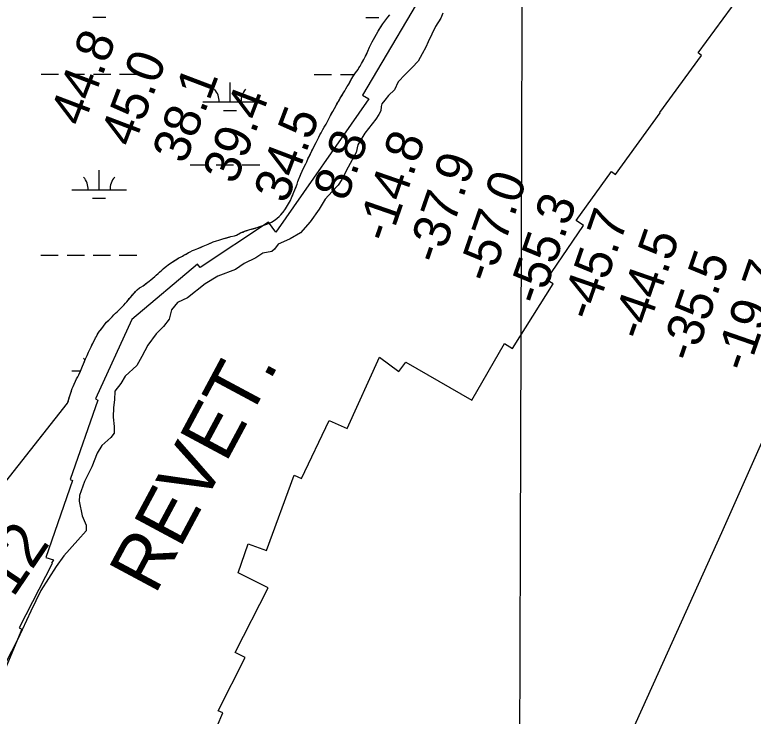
# Model space of a CAD drawing. Extents: x 3148686 to 3186545, y 916144 to 941516.
# Drawn here: x 3159855 to 3161212, y 930448 to 931737 of the extents above; entities that cross this region are included whole.
import ezdxf

# ---------------------------------------------------------------- set-up
doc = ezdxf.new("R2010")
doc.units = 0
for name, color, linetype in [('V-GRID-MAJR', 7, 'Continuous'), ('V-RIVR-EDGE', 7, 'Continuous'), ('V-RIVR-IDEN', 7, 'Continuous'), ('V-RIVR-RANG', 7, 'Continuous'), ('V-RRAP-RVMT', 7, 'Continuous'), ('V-RRAP-RVMT-IDEN', 7, 'Continuous'), ('V-SITE-VEGE', 7, 'Continuous'), ('V-TOPO-BNDY', 7, 'Continuous'), ('V-WETL-SWMP', 7, 'Continuous')]:
    doc.layers.add(name, color=color, linetype=linetype)

msp = doc.modelspace()

# ---------------------------------------------------------------- linework, layer by layer
at = {"layer": 'V-GRID-MAJR'}
msp.add_spline([(3160753.613, 921529.2320000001), (3160773.887, 927589.627), (3160794.169, 933652.633), (3160814.452, 939715.688), (3160814.461, 939718.2490000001)], degree=3, dxfattribs=at)
at = {"layer": 'V-RIVR-EDGE'}
for points in [[(3160641.8411565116, 931740.028499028), (3160637.9178512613, 931730.8187604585), (3160628.306173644, 931715.5949923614), (3160614.76154594, 931687.260977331), (3160610.837363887, 931677.6966470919), (3160604.070310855, 931665.6571895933), (3160596.5896904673, 931651.846527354), (3160585.2138225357, 931640.173059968), (3160572.4160807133, 931627.0847331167), (3160559.6174620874, 931613.6418145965), (3160553.199739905, 931599.4739302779), (3160542.180217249, 931588.5087694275), (3160535.4219322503, 931580.0152286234), (3160529.7326830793, 931573.6466074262), (3160528.6566328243, 931568.6849544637), (3160527.9272830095, 931560.5310996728), (3160524.3647070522, 931553.8026259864), (3160518.6701970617, 931545.3064547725), (3160498.749933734, 931519.8249555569), (3160485.931148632, 931498.2264286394), (3160482.7047514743, 931484.0506530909), (3160468.0998559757, 931457.1376351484), (3160456.3422154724, 931434.4727028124), (3160449.578669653, 931423.8516119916), (3160438.5582701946, 931412.5318594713), (3160425.7578979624, 931398.3797576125), (3160414.3653707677, 931379.9690485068), (3160398.3508766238, 931356.6054544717), (3160380.570438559, 931336.0829778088), (3160361.3961843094, 931325.4925751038)], [(3160361.3961843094, 931325.4925751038), (3160349.3251618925, 931319.4943280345), (3160339.0323586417, 931315.6192469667), (3160332.626034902, 931306.0610543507), (3160327.65122989, 931301.8182295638), (3160311.332121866, 931298.6672374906), (3160298.19206362, 931290.5440708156), (3160276.8902593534, 931279.9589289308), (3160260.905576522, 931268.6514516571), (3160228.2533316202, 931256.6760007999), (3160205.169800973, 931242.5493262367), (3160172.484237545, 931217.0993919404), (3160154.023550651, 931208.2801939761), (3160142.9978903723, 931194.8328914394), (3160138.70070378, 931177.8230129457), (3160128.737941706, 931164.0184883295), (3160115.2301397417, 931150.577323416), (3160099.5763748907, 931129.6949942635), (3160088.887770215, 931109.1549815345), (3160079.271708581, 931092.1582550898), (3160057.947984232, 931072.7083214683), (3160050.1136489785, 931059.2531277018), (3160039.0871118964, 931045.4512334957), (3160038.3384724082, 931029.4963619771), (3160036.884156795, 931014.9616107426), (3160036.1320100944, 930997.5883725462), (3160037.8628818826, 930980.5635883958), (3160037.831316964, 930967.7982882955), (3160031.7848457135, 930960.366768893), (3160015.43680318, 930945.5142517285), (3160006.5369393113, 930931.352505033), (3159996.8998343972, 930905.8455785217), (3159983.35959071, 930879.2845218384), (3159974.4307923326, 930853.421250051), (3159973.6953048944, 930842.7852535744), (3159978.947542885, 930815.8231346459), (3159986.706473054, 930798.7834448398), (3159986.6810457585, 930788.5002864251), (3159971.036925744, 930771.518465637), (3159945.0798360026, 930742.5059553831), (3159931.557128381, 930723.036732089), (3159903.0801944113, 930678.7829176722), (3159884.5467328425, 930640.5326111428), (3159861.0174229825, 930589.5292797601), (3159837.5021419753, 930544.1994150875)]]:
    msp.add_lwpolyline(points, dxfattribs=at)
at = {"layer": 'V-RRAP-RVMT'}
for points in [[(3160778.362000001, 932090.9169999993), (3160623.011000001, 931820.1139999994), (3160628.223000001, 931816.6929999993), (3160494.3570000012, 931589.4709999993), (3160505.799000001, 931582.6299999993), (3160335.192000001, 931337.4799999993), (3160321.716000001, 931355.9769999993), (3160196.112000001, 931272.4869999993), (3160190.900000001, 931278.4419999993), (3160070.636000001, 931176.8989999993), (3160003.384000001, 931030.8869999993), (3160007.834000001, 931028.7969999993), (3159956.918000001, 930882.8799999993), (3159961.494000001, 930881.2329999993), (3159912.106000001, 930739.7519999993), (3159926.120000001, 930735.1229999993), (3159923.006000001, 930729.0119999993), (3159923.647000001, 930728.6839999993), (3159863.236000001, 930610.1979999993), (3159868.342000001, 930607.6079999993), (3159814.852000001, 930481.5139999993)], [(3160265.567000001, 930711.5469999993), (3160284.251000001, 930764.4829999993), (3160318.063000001, 930752.0679999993), (3160368.908000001, 930890.7779999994), (3160382.382000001, 930884.9509999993), (3160432.973000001, 930991.4859999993), (3160466.277000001, 930976.5379999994), (3160525.765000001, 931107.6479999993), (3160560.848000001, 931081.2989999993), (3160573.811000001, 931098.6799999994), (3160695.159000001, 931028.6119999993), (3160755.409000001, 931132.9829999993), (3160770.137000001, 931123.7439999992), (3160844.331000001, 931242.4809999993), (3160832.660000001, 931249.8039999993), (3160900.153000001, 931349.9039999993), (3160886.722000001, 931358.9559999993), (3160952.015000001, 931448.8319999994), (3160958.946000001, 931443.7649999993), (3161041.253000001, 931557.0439999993), (3161040.915000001, 931557.2889999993), (3161117.333000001, 931662.4569999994), (3161111.1780000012, 931666.9029999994), (3161187.612000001, 931772.0799999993)], [(3159946.181000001, 929558.8359999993), (3159956.159000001, 929554.5989999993), (3160010.860000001, 929683.4019999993), (3159995.416000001, 929689.9789999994), (3160047.447000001, 929812.3709999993), (3160034.780000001, 929817.7679999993), (3160086.752000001, 929940.1549999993), (3160053.551000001, 929954.3769999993), (3160105.559000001, 930076.7079999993), (3160092.637000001, 930082.2549999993), (3160144.613000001, 930204.6469999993), (3160142.062000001, 930205.7159999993), (3160194.031000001, 930328.1279999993), (3160185.721000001, 930331.6589999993), (3160237.700000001, 930454.0649999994), (3160228.971000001, 930457.8329999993), (3160278.719000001, 930555.5589999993), (3160260.308000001, 930564.9589999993), (3160320.700000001, 930683.4469999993), (3160265.567000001, 930711.5469999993)]]:
    msp.add_lwpolyline(points, dxfattribs=at)
at = {"layer": 'V-SITE-VEGE'}
for p, q in [((3160540.677, 931732.7579999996), (3160544.257, 931737.1839999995)), ((3160531.543, 931720.2939999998), (3160540.677, 931732.7579999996)), ((3160523.0130000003, 931706.8359999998), (3160531.543, 931720.2939999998)), ((3160512.116, 931687.5559999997), (3160519.843, 931701.4129999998)), ((3160519.843, 931701.4129999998), (3160523.0130000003, 931706.8359999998)), ((3160507.3680000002, 931677.7219999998), (3160512.116, 931687.5559999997)), ((3160499.86, 931660.8609999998), (3160504.21, 931670.0949999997)), ((3160504.21, 931670.0949999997), (3160507.3680000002, 931677.7219999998)), ((3160496.694, 931654.6409999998), (3160499.86, 931660.8609999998)), ((3160487.773, 931639.5759999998), (3160489.958, 931642.5909999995)), ((3160489.958, 931642.5909999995), (3160492.5330000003, 931647.4099999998)), ((3160492.5330000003, 931647.4099999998), (3160496.694, 931654.6409999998)), ((3160478.842, 931626.7139999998), (3160481.4220000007, 931630.1309999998)), ((3160481.4220000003, 931630.1309999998), (3160485.989, 931636.7639999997)), ((3160485.989, 931636.7639999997), (3160487.773, 931639.5759999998)), ((3160468.1410000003, 931608.0369999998), (3160473.488, 931617.8749999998)), ((3160473.488, 931617.8749999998), (3160476.659, 931623.2979999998)), ((3160476.659, 931623.2979999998), (3160478.842, 931626.7139999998)), ((3160463.779, 931600.8049999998), (3160466.355, 931605.2229999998)), ((3160466.355, 931605.2229999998), (3160468.1410000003, 931608.0369999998)), ((3160453.467, 931583.9319999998), (3160459.615, 931593.9729999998)), ((3160459.615, 931593.9729999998), (3160461.596, 931597.5899999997)), ((3160461.596, 931597.5899999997), (3160463.779, 931600.8049999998)), ((3160442.568, 931565.0529999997), (3160453.467, 931583.9319999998)), ((3160439.598, 931559.6299999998), (3160442.568, 931565.0529999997)), ((3160430.29, 931542.3629999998), (3160435.238, 931551.9989999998)), ((3160435.238, 931551.9989999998), (3160439.598, 931559.6299999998)), ((3160423.554, 931530.3129999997), (3160427.324, 931536.3399999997)), ((3160427.324, 931536.3399999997), (3160430.29, 931542.3629999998)), ((3160415.829, 931516.2579999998), (3160418.008, 931520.0729999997)), ((3160418.008, 931520.0729999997), (3160421.174, 931526.2969999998)), ((3160421.174, 931526.2969999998), (3160423.554, 931530.3129999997)), ((3160408.9050000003, 931502.2059999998), (3160413.8510000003, 931512.0429999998)), ((3160413.8510000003, 931512.0429999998), (3160415.829, 931516.2579999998)), ((3160400.987, 931486.7479999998), (3160406.926, 931497.9919999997)), ((3160406.926, 931497.9919999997), (3160408.9050000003, 931502.2059999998)), ((3160394.659, 931473.5019999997), (3160400.987, 931486.7479999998)), ((3160389.916, 931462.8619999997), (3160391.894, 931467.0789999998)), ((3160391.894, 931467.0789999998), (3160394.659, 931473.5019999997)), ((3160383.387, 931449.8139999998), (3160387.736, 931459.0469999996)), ((3160387.736, 931459.0469999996), (3160389.916, 931462.8619999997)), ((3160375.489, 931430.9519999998), (3160381.015, 931444.3929999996)), ((3160381.015, 931444.3929999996), (3160383.387, 931449.8139999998)), ((3160369.9760000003, 931415.1089999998), (3160373.917, 931425.9409999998)), ((3160373.917, 931425.9409999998), (3160375.489, 931430.9519999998)), ((3160363.857, 931400.4619999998), (3160368.197, 931411.2959999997)), ((3160368.197, 931411.2959999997), (3160369.9760000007, 931415.1089999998)), ((3160361.68, 931396.0439999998), (3160363.857, 931400.4619999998)), ((3160354.348, 931383.3919999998), (3160358.313, 931389.8199999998)), ((3160358.313, 931389.8199999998), (3160361.68, 931396.0439999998)), ((3160344.221, 931369.3219999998), (3160348.593, 931374.5499999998)), ((3160348.593, 931374.5499999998), (3160352.7630000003, 931380.5779999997)), ((3160352.7630000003, 931380.5779999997), (3160354.348, 931383.3919999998)), ((3160326.882, 931356.0099999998), (3160333.4620000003, 931360.4519999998)), ((3160333.4620000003, 931360.4519999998), (3160341.036, 931366.0999999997)), ((3160341.036, 931366.0999999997), (3160344.221, 931369.3219999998)), ((3160286.93, 931342.1669999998), (3160300.518, 931345.8499999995)), ((3160300.518, 931345.8499999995), (3160305.5130000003, 931347.6789999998)), ((3160305.5130000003, 931347.6789999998), (3160314.703, 931350.7339999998)), ((3160314.703, 931350.7339999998), (3160318.498, 931352.1579999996)), ((3160318.498, 931352.1579999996), (3160326.882, 931356.0099999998)), ((3160252.1750000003, 931329.3549999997), (3160258.772, 931330.996)), ((3160258.772, 931330.9959999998), (3160262.966, 931332.2199999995)), ((3160262.966, 931332.2199999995), (3160270.151, 931336.0639999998)), ((3160270.151, 931336.0639999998), (3160277.339, 931339.1099999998)), ((3160277.339, 931339.1099999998), (3160286.93, 931342.1669999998)), ((3160210.6210000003, 931315.5019999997), (3160219.805, 931319.56)), ((3160219.805, 931319.5599999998), (3160226, 931321.3969999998)), ((3160226, 931321.3969999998), (3160229.9930000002, 931322.8219999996)), ((3160229.9930000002, 931322.8219999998), (3160233.991, 931324.0469999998)), ((3160233.991, 931324.0469999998), (3160237.784, 931325.4679999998)), ((3160237.784, 931325.4679999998), (3160252.1750000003, 931329.3549999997)), ((3160177.673, 931301.4999999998), (3160182.0640000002, 931303.7279999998)), ((3160182.0640000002, 931303.7279999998), (3160185.46, 931305.1499999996)), ((3160185.46, 931305.1499999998), (3160188.657, 931306.1679999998)), ((3160188.657, 931306.1679999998), (3160191.653, 931307.3859999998)), ((3160191.653, 931307.3859999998), (3160201.434, 931311.6459999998)), ((3160201.434, 931311.6459999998), (3160207.623, 931314.4849999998)), ((3160207.623, 931314.4849999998), (3160210.6210000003, 931315.5019999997)), ((3160144.156, 931282.6909999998), (3160156.722, 931290.3689999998)), ((3160156.722, 931290.3689999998), (3160160.714, 931292.194)), ((3160160.714, 931292.1939999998), (3160163.507, 931293.6109999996)), ((3160163.507, 931293.6109999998), (3160166.102, 931295.2289999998)), ((3160166.102, 931295.2289999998), (3160177.673, 931301.4999999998)), ((3160133.793, 931274.8249999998), (3160137.178, 931277.6469999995)), ((3160137.178, 931277.6469999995), (3160144.156, 931282.6909999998)), ((3160112.481, 931256.2889999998), (3160125.4250000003, 931267.9699999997)), ((3160125.4250000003, 931267.9699999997), (3160131.401, 931273.0109999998)), ((3160131.401, 931273.0109999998), (3160133.793, 931274.8249999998)), ((3160101.926, 931247.4189999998), (3160105.311, 931250.0379999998)), ((3160105.311, 931250.0379999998), (3160108.897, 931253.2639999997)), ((3160108.897, 931253.2639999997), (3160112.481, 931256.2889999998)), ((3160080.397, 931231.6799999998), (3160084.383, 931235.1059999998)), ((3160084.383, 931235.1059999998), (3160087.174, 931236.7220000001)), ((3160087.174, 931236.7219999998), (3160090.9650000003, 931239.1469999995)), ((3160090.965, 931239.1469999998), (3160099.536, 931245.4029999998)), ((3160099.536, 931245.4029999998), (3160101.926, 931247.4189999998)), ((3160063.294, 931212.5659999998), (3160074.427, 931225.6399999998)), ((3160074.427, 931225.6399999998), (3160080.397, 931231.6799999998)), ((3160058.721, 931207.1349999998), (3160060.911, 931209.5489999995)), ((3160060.911, 931209.5489999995), (3160063.294, 931212.5659999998)), ((3160043.2060000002, 931191.0309999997), (3160047.582, 931195.2599999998)), ((3160047.582, 931195.2599999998), (3160055.543, 931203.3129999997)), ((3160055.543, 931203.3129999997), (3160058.721, 931207.1349999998)), ((3160030.666, 931178.3479999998), (3160034.446, 931182.1739999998)), ((3160034.446, 931182.1739999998), (3160037.2290000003, 931185.3929999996)), ((3160037.2290000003, 931185.3929999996), (3160040.414, 931188.6119999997)), ((3160040.414, 931188.6119999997), (3160043.2060000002, 931191.0309999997)), ((3160015.156, 931160.4419999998), (3160021.312, 931168.8859999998)), ((3160021.312, 931168.8859999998), (3160023.897, 931171.9049999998)), ((3160023.897, 931171.9049999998), (3160030.666, 931178.3479999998)), ((3160008.201, 931151.7939999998), (3160011.181, 931155.6149999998)), ((3160011.181, 931155.6149999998), (3160015.156, 931160.4419999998)), ((3159998.703, 931132.7249999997), (3160003.448, 931143.1609999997)), ((3160003.448, 931143.1609999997), (3160005.232, 931145.9729999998)), ((3160005.232, 931145.9729999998), (3160006.616, 931148.9839999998)), ((3160006.616, 931148.9839999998), (3160008.201, 931151.7939999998)), ((3159993.361, 931122.0849999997), (3159998.703, 931132.7249999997)), ((3159988.223, 931110.6449999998), (3159989.603, 931114.0569999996)), ((3159989.603, 931114.0569999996), (3159990.99, 931116.8669999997)), ((3159990.99, 931116.8669999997), (3159993.361, 931122.0849999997)), ((3159975.98, 931081.7519999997), (3159985.454, 931104.6259999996)), ((3159985.454, 931104.6259999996), (3159988.223, 931110.6449999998)), ((3159971.034, 931071.5139999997), (3159972.8140000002, 931075.5279999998)), ((3159972.8140000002, 931075.5279999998), (3159975.98, 931081.7519999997)), ((3159964.108, 931057.8619999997), (3159967.077, 931063.6839999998)), ((3159967.077, 931063.6839999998), (3159968.855, 931067.6989999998)), ((3159968.855, 931067.6989999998), (3159971.034, 931071.5139999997)), ((3159957.994, 931042.0149999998), (3159960.95, 931050.4379999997)), ((3159960.95, 931050.4379999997), (3159962.328, 931054.0509999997)), ((3159962.328, 931054.0509999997), (3159964.1080000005, 931057.8619999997)), ((3159952.393, 931023.0989999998), (3159957.994, 931042.0149999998)), ((3159838.7090000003, 930879.0899999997), (3159952.3930000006, 931023.0989999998))]:
    msp.add_line(p, q, dxfattribs=at)
at = {"layer": 'V-TOPO-BNDY'}
msp.add_lwpolyline([(3159006.1799390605, 926311.1140521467), (3159280.923117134, 926819.7200949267), (3159355.150214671, 926960.9429210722), (3159433.8874771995, 927110.7463134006), (3159462.311762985, 927164.6156961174), (3160176.095636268, 928634.9638413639), (3160389.8208180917, 929116.3938288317), (3160397.8632753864, 929134.5112612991), (3160404.645886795, 929149.1810180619), (3160858.7482387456, 930130.395099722), (3161037.620413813, 930526.531847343), (3161154.717499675, 930785.7311076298), (3161271.8932987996, 931050.1815064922), (3161316.07247631, 931173.5953326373), (3161356.8274845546, 931287.541667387), (3161429.0231613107, 931551.0205764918), (3161684.43194303, 932501.7157914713), (3161786.667924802, 932820.8756396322), (3161812.492075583, 932901.8922822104), (3162033.7169010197, 933562.9397132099)], dxfattribs=at)
at = {"layer": 'V-WETL-SWMP'}
for p, q in [((3159998.5671104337, 931732.5416555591), (3160022.5670971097, 931732.5163666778)), ((3160500.4748318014, 931732.0127933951), (3160524.474818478, 931731.9875045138)), ((3159903.612903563, 931628.0016510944), (3159935.612885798, 931627.9679325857)), ((3159951.6128769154, 931627.9510733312), (3159983.612859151, 931627.9173548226)), ((3159999.6128502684, 931627.9004955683), (3160031.6128325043, 931627.8667770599)), ((3160047.612823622, 931627.8499178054), (3160079.612805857, 931627.8161992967)), ((3160405.5206249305, 931627.4727889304), (3160437.520607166, 931627.4390704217)), ((3160453.520598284, 931627.4222111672), (3160479.3555779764, 931627.3949887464)), ((3160250.875243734, 931576.893711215), (3160250.9131770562, 931612.8936912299)), ((3160200.8752714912, 931576.9463963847), (3160300.875215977, 931576.8410260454)), ((3160238.858990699, 931561.4753642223), (3160262.858977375, 931561.450075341)), ((3160177.3456533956, 931461.5391255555), (3160209.345635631, 931461.5054070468)), ((3160225.3456267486, 931461.4885477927), (3160257.345608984, 931461.4548292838)), ((3160273.3456001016, 931461.4379700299), (3160305.345582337, 931461.4042515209)), ((3160010.232822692, 931415.2851872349), (3160010.270756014, 931451.28516725)), ((3159960.2328504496, 931415.3378724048), (3160060.2327949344, 931415.232502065)), ((3159998.2165696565, 931399.8668402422), (3160022.2165563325, 931399.8415513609)), ((3159903.2623627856, 931295.3268357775), (3159935.2623450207, 931295.2931172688)), ((3159951.262336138, 931295.2762580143), (3159983.2623183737, 931295.2425395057)), ((3159999.262309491, 931295.2256802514), (3160031.262291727, 931295.1919617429)), ((3160047.2622828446, 931295.1751024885), (3160079.2622650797, 931295.1413839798)), ((3159959.8823096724, 931082.6630570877), (3159976.3530843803, 931082.6457017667)), ((3159902.911822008, 930962.6520204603), (3159904.6730085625, 930962.650164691))]:
    msp.add_line(p, q, dxfattribs=at)
msp.add_lwpolyline([(3159838.708, 930879.09), (3159952.394, 931023.1), (3159954.077, 931027.18), (3159955.4430000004, 931033.393), (3159956.4239999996, 931036.801), (3159957.9950000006, 931042.0149999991), (3159959.1759999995, 931045.424), (3159960.9489999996, 931050.4389999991), (3159962.329, 931054.05), (3159964.1080000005, 931057.863000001), (3159967.077, 931063.685), (3159968.8550000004, 931067.699), (3159971.035, 931071.514), (3159972.813, 931075.528), (3159975.98, 931081.752000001), (3159978.7440000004, 931088.373), (3159981.506, 931095.195000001), (3159983.48, 931100.01), (3159985.455, 931104.6249999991), (3159988.223, 931110.6460000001), (3159989.6040000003, 931114.057), (3159990.989, 931116.867), (3159993.361, 931122.085), (3159995.736, 931126.703), (3159997.1210000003, 931129.513), (3159998.7029999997, 931132.724999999), (3160001.471, 931138.746), (3160003.447, 931143.161), (3160005.232, 931145.974), (3160006.6159999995, 931148.984), (3160008.201, 931151.796000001), (3160011.1809999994, 931155.616), (3160013.1690000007, 931158.0299999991), (3160015.157, 931160.443), (3160018.136, 931164.464), (3160021.313, 931168.885999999), (3160023.8969999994, 931171.904000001), (3160028.078, 931175.931), (3160030.666, 931178.3480000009), (3160034.4469999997, 931182.1730000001), (3160037.2299999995, 931185.3919999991), (3160040.414, 931188.613), (3160043.203, 931191.0310000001), (3160047.582, 931195.2600000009), (3160050.3680000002, 931198.078), (3160052.5569999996, 931200.2930000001), (3160055.5420000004, 931203.312999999), (3160058.722, 931207.134), (3160060.9099999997, 931209.549), (3160063.295, 931212.5650000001), (3160065.6800000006, 931215.381000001), (3160069.0600000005, 931219.404000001), (3160071.8440000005, 931222.6229999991), (3160074.428, 931225.640000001), (3160077.015, 931228.258), (3160080.3980000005, 931231.68), (3160084.3820000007, 931235.106), (3160087.1750000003, 931236.723), (3160090.964, 931239.147), (3160095.748, 931242.577999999), (3160099.535, 931245.402), (3160101.9250000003, 931247.4180000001), (3160105.3120000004, 931250.039), (3160108.8970000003, 931253.263), (3160112.482, 931256.286), (3160115.0699999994, 931258.702999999), (3160118.4560000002, 931261.724999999), (3160121.244, 931264.143), (3160125.4250000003, 931267.971), (3160127.816, 931269.986), (3160131.401, 931273.0099999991), (3160133.7930000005, 931274.825000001), (3160137.179, 931277.647), (3160141.365, 931280.6739999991), (3160144.156, 931282.691), (3160148.544, 931285.319), (3160152.134, 931287.542), (3160156.722, 931290.3700000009), (3160160.714, 931292.194999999), (3160163.5080000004, 931293.612000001), (3160166.1010000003, 931295.2289999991), (3160169.893, 931297.252), (3160174.6809999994, 931299.882), (3160177.674, 931301.501000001), (3160182.0649999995, 931303.728), (3160185.46, 931305.149), (3160188.657, 931306.1680000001), (3160191.6520000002, 931307.387), (3160196.643, 931309.617000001), (3160201.4350000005, 931311.647), (3160207.6239999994, 931314.4850000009), (3160210.621, 931315.503), (3160216.011, 931317.9369999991), (3160219.8050000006, 931319.56), (3160225.999, 931321.397), (3160229.994, 931322.821), (3160233.991, 931324.046000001), (3160237.785, 931325.469), (3160242.382, 931326.696), (3160249.177, 931328.537), (3160252.1750000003, 931329.355), (3160258.771, 931330.9950000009), (3160262.9670000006, 931332.22), (3160266.759, 931334.2440000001), (3160270.151, 931336.064999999), (3160274.1450000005, 931337.6889999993), (3160277.339, 931339.1089999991), (3160280.336, 931340.127), (3160286.929, 931342.167000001), (3160290.127, 931342.9859999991), (3160293.1249999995, 931343.8039999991), (3160297.3210000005, 931345.03), (3160300.5190000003, 931345.849), (3160305.5130000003, 931347.679), (3160309.9080000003, 931349.106000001), (3160314.703, 931350.735), (3160318.498, 931352.158000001), (3160322.49, 931353.983), (3160326.8820000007, 931356.0099999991), (3160330.471, 931358.4330000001), (3160333.4620000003, 931360.452), (3160337.8469999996, 931363.68), (3160341.036, 931366.1), (3160344.22, 931369.3209999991), (3160346.207, 931371.734999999), (3160348.593, 931374.551000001), (3160352.762, 931380.5800000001), (3160354.347, 931383.3910000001), (3160358.313, 931389.820000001), (3160361.679, 931396.044), (3160363.8560000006, 931400.461), (3160366.224, 931406.279), (3160368.197, 931411.295000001), (3160369.9760000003, 931415.108), (3160372.144, 931420.926), (3160373.916, 931425.9400000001), (3160375.489, 931430.952999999), (3160377.858, 931436.572), (3160379.4360000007, 931440.584), (3160381.0150000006, 931444.3960000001), (3160383.386, 931449.814999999), (3160385.957, 931455.234), (3160387.736, 931459.047), (3160389.9159999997, 931462.8629999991), (3160391.893, 931467.078), (3160394.6580000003, 931473.498999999), (3160396.637, 931477.514), (3160398.416, 931481.328), (3160400.9869999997, 931486.747), (3160402.769, 931490.160000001), (3160404.749, 931493.775000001), (3160406.9269999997, 931497.991), (3160408.904, 931502.2059999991), (3160410.883, 931506.02), (3160413.8510000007, 931512.042000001), (3160415.828, 931516.257), (3160418.008, 931520.073), (3160421.1750000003, 931526.297), (3160423.553000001, 931530.3139999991), (3160427.322, 931536.3409999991), (3160430.2889999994, 931542.3629999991), (3160432.269, 931546.177), (3160435.237, 931551.9990000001), (3160437.417, 931555.8150000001), (3160439.5970000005, 931559.631000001), (3160442.568, 931565.0530000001), (3160445.1450000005, 931569.471), (3160447.324, 931573.287), (3160451.0899999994, 931579.714), (3160453.468, 931583.931), (3160456.244, 931588.351), (3160459.6150000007, 931593.975), (3160461.595, 931597.59), (3160463.779, 931600.805000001), (3160466.355, 931605.223), (3160468.14, 931608.036), (3160470.121, 931611.6510000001), (3160471.9039999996, 931614.864000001), (3160473.488, 931617.875), (3160475.073, 931620.6869999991), (3160476.659, 931623.2980000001), (3160478.8410000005, 931626.714), (3160481.423, 931630.1309999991), (3160483.21, 931632.7440000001), (3160485.9889999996, 931636.763), (3160487.774, 931639.576), (3160489.958, 931642.591), (3160492.5330000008, 931647.41), (3160494.514, 931650.824), (3160496.694, 931654.64), (3160499.861, 931660.863000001), (3160502.036, 931665.479999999), (3160504.211, 931670.096), (3160507.3689999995, 931677.721), (3160509.544, 931682.337000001), (3160512.116, 931687.557), (3160516.6720000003, 931695.79), (3160519.8420000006, 931701.4130000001), (3160523.014, 931706.836), (3160528.1709999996, 931714.872), (3160531.543, 931720.296), (3160535.3160000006, 931725.5220000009), (3160540.678, 931732.759), (3160544.256, 931737.184)], dxfattribs=at)
for centre, radius, start, end in [((3160195.6328386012, 931577.4267238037), 35.24628790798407, 359.1678071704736, 40.711465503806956), ((3160306.1186494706, 931577.3103044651), 35.246287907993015, 139.16780416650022, 180.71146249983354), ((3159954.9904175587, 931415.8181998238), 35.24628790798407, 359.1678071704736, 40.711465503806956), ((3160065.476228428, 931415.7017804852), 35.246287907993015, 139.16780416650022, 180.71146249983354), ((3159954.6398767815, 931083.1433845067), 35.24628790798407, 32.499853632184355, 40.711465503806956)]:
    msp.add_arc(centre, radius, start, end, dxfattribs=at)

# ---------------------------------------------------------------- texts
at = {"layer": 'V-RIVR-IDEN'}
msp.add_text('2012', height=82.99983199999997, rotation=55.83125603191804, dxfattribs=at).set_placement((3159782.558221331, 930561.892457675))
at = {"layer": 'V-RIVR-RANG'}
for s, height, rotation, p in [('44.8', 67.00000000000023, 69.18832571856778, (3159980.321150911, 931529.3475830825)), ('45.0', 67.00000000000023, 69.18832571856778, (3160072.8512288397, 931491.3323264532)), ('38.1', 67.00000000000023, 69.18832571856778, (3160168.287632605, 931460.9607021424)), ('39.4', 67.00000000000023, 69.18832571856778, (3160261.005150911, 931423.4385830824)), ('34.5', 67.00000000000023, 69.18832571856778, (3160354.566150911, 931388.1355830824)), ('8.8', 67, 70.87416666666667, (3160465.0426557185, 931392.3532438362)), ('-14.8', 67, 70.87416666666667, (3160543.827778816, 931315.8379875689)), ('-37.9', 67, 70.87416666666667, (3160636.2033695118, 931276.1932465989)), ('-57.0', 67, 70.87416666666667, (3160730.0316514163, 931241.637119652)), ('-55.3', 67, 70.87416666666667, (3160821.690060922, 931200.8477674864)), ('-45.7', 67, 70.87416666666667, (3160917.500333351, 931172.0279357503)), ('-44.5', 67, 70.87416666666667, (3161010.8232273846, 931135.9674615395)), ('-35.5', 67, 70.87416666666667, (3161102.6544778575, 931095.6765174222)), ('-19.7', 67, 70.87416666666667, (3161202.1574488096, 931077.8641833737))]:
    msp.add_text(s, height=height, rotation=rotation, dxfattribs=at).set_placement(p)
at = {"layer": 'V-RRAP-RVMT-IDEN'}
msp.add_text('REVET.', height=99.99980200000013, rotation=61.80810425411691, dxfattribs=at).set_placement((3160113.0070819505, 930669.284849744))

doc.saveas('drawing.dxf')
